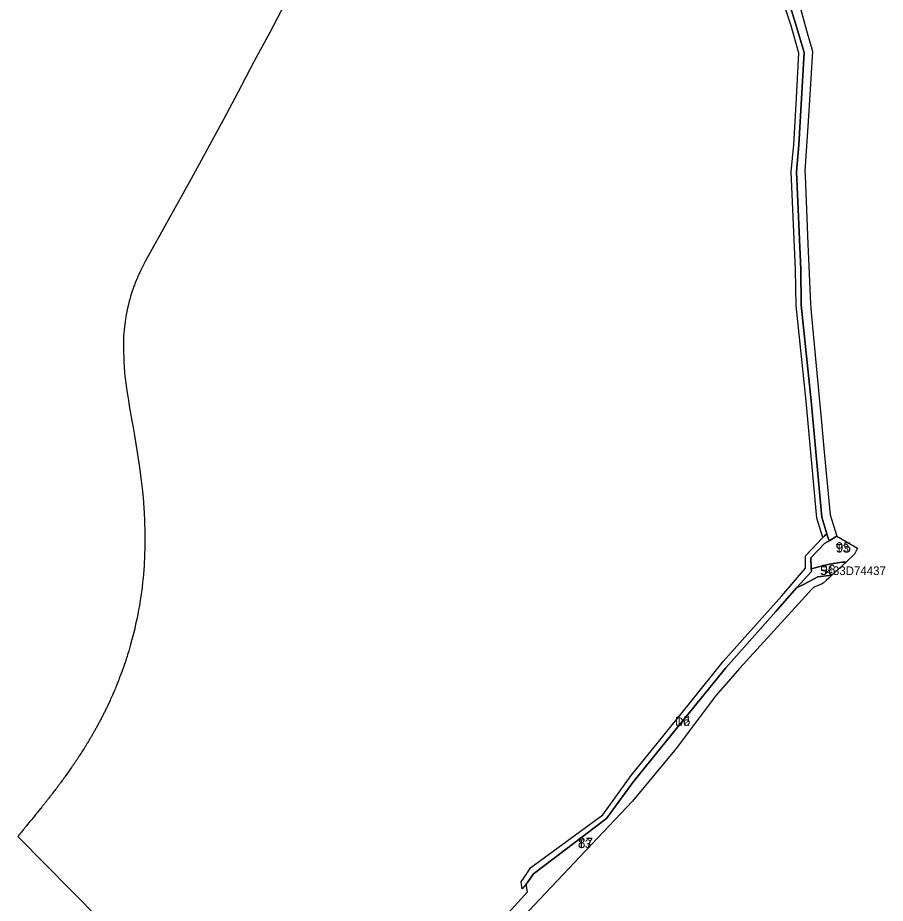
# Model space of a CAD drawing. Extents: x -537012 to -534603, y -1176562 to -1172739.
# Drawn here: x -536047 to -535541, y -1174648 to -1174132 of the extents above; entities that cross this region are included whole.
import ezdxf

# ---------------------------------------------------------------- set-up
doc = ezdxf.new("R2010")
doc.units = 0
for name, color, linetype in [('96120023', 7, 'Continuous'), ('96140023', 7, 'Continuous'), ('ID_VPS', 7, 'Continuous')]:
    doc.layers.add(name, color=color, linetype=linetype)

msp = doc.modelspace()

# ---------------------------------------------------------------- linework, layer by layer
at = {"layer": '96120023'}
for points in [[(-535891.53, -1174123.6), (-535900.28, -1174140.39), (-535909.37, -1174157.17), (-535919.16, -1174175.71), (-535927.21, -1174191.1), (-535946.09, -1174225.72), (-535972.84, -1174273.97), (-535973.9, -1174275.96), (-535974.53, -1174277.12), (-535974.84, -1174277.72), (-535975.24, -1174278.53), (-535975.67, -1174279.4), (-535976.07, -1174280.25), (-535976.35, -1174280.83), (-535976.73, -1174281.67), (-535977.01, -1174282.31), (-535977.27, -1174282.88), (-535977.37, -1174283.13), (-535977.48, -1174283.36), (-535977.5, -1174283.43), (-535977.53, -1174283.5), (-535977.56, -1174283.56), (-535977.58, -1174283.62), (-535977.6, -1174283.66), (-535977.63, -1174283.72), (-535977.66, -1174283.79), (-535977.69, -1174283.87), (-535977.72, -1174283.93), (-535977.73, -1174283.97), (-535977.81, -1174284.14), (-535977.89, -1174284.34), (-535977.93, -1174284.44), (-535978.03, -1174284.68), (-535978.16, -1174284.98), (-535978.26, -1174285.23), (-535978.35, -1174285.47), (-535978.58, -1174286.03), (-535978.72, -1174286.4), (-535978.97, -1174287.02), (-535979.24, -1174287.74), (-535979.46, -1174288.39), (-535979.94, -1174289.65), (-535980.49, -1174291.25), (-535981.01, -1174292.89), (-535981.47, -1174294.4), (-535981.93, -1174295.97), (-535982.21, -1174297.02), (-535982.72, -1174298.92), (-535983.04, -1174300.36), (-535983.44, -1174302.16), (-535983.81, -1174304.02), (-535984.18, -1174306.05), (-535984.66, -1174309.2), (-535985.05, -1174312.04), (-535985.49, -1174317.46), (-535985.58, -1174326.03), (-535985.4, -1174330.79), (-535985.37, -1174332.48), (-535985.21, -1174335.55), (-535984.98, -1174338.43), (-535984.73, -1174340.89), (-535984.44, -1174343.35), (-535984.24, -1174344.91), (-535984.07, -1174346.15), (-535983.79, -1174348.09), (-535983.24, -1174351.73), (-535982.73, -1174354.88), (-535982.18, -1174358.19), (-535981.62, -1174361.4), (-535980.68, -1174366.79), (-535979.99, -1174370.69), (-535979.16, -1174375.44), (-535978.54, -1174379.1), (-535977.73, -1174383.96), (-535976.93, -1174389.07), (-535976.21, -1174394.02), (-535975.23, -1174401.58), (-535974.52, -1174407.91), (-535973.96, -1174414.06), (-535973.93, -1174414.51), (-535973.89, -1174414.96), (-535973.85, -1174415.41), (-535973.82, -1174415.87), (-535973.79, -1174416.32), (-535973.75, -1174416.78), (-535973.72, -1174417.23), (-535973.63, -1174418.61), (-535973.57, -1174419.54), (-535973.43, -1174421.87), (-535973.34, -1174423.76), (-535973.25, -1174425.67), (-535973.09, -1174431.51), (-535973.09, -1174440.09), (-535973.53, -1174451.08), (-535973.74, -1174453.87), (-535973.92, -1174456.32), (-535974.14, -1174458.55), (-535974.4, -1174460.96), (-535974.7, -1174463.8), (-535974.92, -1174465.59), (-535975.27, -1174467.86), (-535975.62, -1174470.51), (-535976.06, -1174472.91), (-535976.32, -1174474.79), (-535976.8, -1174477.15), (-535977.24, -1174479.82), (-535977.81, -1174482.49), (-535978.51, -1174485.37), (-535979.03, -1174488.26), (-535979.91, -1174491.58), (-535980.61, -1174494.47), (-535981.66, -1174498.05), (-535982.53, -1174501.11), (-535983.14, -1174503.12), (-535983.51, -1174504.29), (-535983.98, -1174505.75), (-535984.29, -1174506.7), (-535986.55, -1174513.28), (-535987.3, -1174515.29), (-535987.6, -1174516.05), (-535988.02, -1174517.16), (-535988.33, -1174518), (-535988.71, -1174518.94), (-535989.24, -1174520.28), (-535989.6, -1174521.18), (-535989.89, -1174521.88), (-535990.18, -1174522.58), (-535990.5, -1174523.37), (-535991.02, -1174524.56), (-535991.54, -1174525.8), (-535991.98, -1174526.78), (-535992.48, -1174527.97), (-535993.05, -1174529.17), (-535993.4, -1174530.02), (-535995.11, -1174533.63), (-535995.31, -1174534.06), (-535995.54, -1174534.54), (-535995.78, -1174535.02), (-535996.01, -1174535.51), (-535996.25, -1174535.98), (-535996.48, -1174536.46), (-535996.72, -1174536.94), (-535996.96, -1174537.41), (-535997.2, -1174537.89), (-535997.44, -1174538.36), (-535997.68, -1174538.83), (-535997.91, -1174539.3), (-535998.15, -1174539.76), (-535998.4, -1174540.23), (-535998.64, -1174540.69), (-535998.88, -1174541.16), (-535999.12, -1174541.62), (-535999.36, -1174542.08), (-535999.61, -1174542.53), (-535999.85, -1174542.99), (-536000.09, -1174543.44), (-536000.34, -1174543.89), (-536000.58, -1174544.35), (-536000.83, -1174544.8), (-536001.07, -1174545.24), (-536001.32, -1174545.69), (-536001.56, -1174546.13), (-536001.81, -1174546.58), (-536002.06, -1174547.02), (-536002.3, -1174547.46), (-536002.55, -1174547.9), (-536002.8, -1174548.33), (-536003.05, -1174548.77), (-536003.3, -1174549.2), (-536003.54, -1174549.64), (-536003.79, -1174550.07), (-536004.04, -1174550.49), (-536004.29, -1174550.92), (-536004.54, -1174551.35), (-536004.79, -1174551.77), (-536005.04, -1174552.2), (-536005.29, -1174552.62), (-536005.54, -1174553.04), (-536005.79, -1174553.46), (-536006.04, -1174553.87), (-536006.54, -1174554.7), (-536006.79, -1174555.12), (-536007.04, -1174555.53), (-536007.55, -1174556.35), (-536007.8, -1174556.75), (-536008.05, -1174557.16), (-536008.55, -1174557.96), (-536009.06, -1174558.76), (-536009.81, -1174559.95), (-536010.32, -1174560.74), (-536011.32, -1174562.29), (-536012.08, -1174563.45), (-536012.33, -1174563.83), (-536012.58, -1174564.21), (-536012.83, -1174564.58), (-536013.09, -1174564.96), (-536013.34, -1174565.34), (-536013.59, -1174565.71), (-536013.84, -1174566.08), (-536014.09, -1174566.45), (-536014.34, -1174566.82), (-536014.59, -1174567.19), (-536014.84, -1174567.56), (-536015.09, -1174567.93), (-536015.34, -1174568.29), (-536015.59, -1174568.65), (-536015.84, -1174569.02), (-536016.59, -1174570.09), (-536017.59, -1174571.51), (-536018.58, -1174572.91), (-536019.57, -1174574.29), (-536019.82, -1174574.63), (-536020.31, -1174575.3), (-536020.8, -1174575.98), (-536021.29, -1174576.65), (-536021.77, -1174577.31), (-536022.26, -1174577.97), (-536022.5, -1174578.29), (-536022.75, -1174578.62), (-536022.99, -1174578.95), (-536023.23, -1174579.27), (-536023.47, -1174579.59), (-536023.71, -1174579.91), (-536023.98, -1174580.27), (-536024.22, -1174580.59), (-536024.7, -1174581.22), (-536025.17, -1174581.85), (-536025.65, -1174582.48), (-536026.12, -1174583.09), (-536027.06, -1174584.32), (-536027.3, -1174584.62), (-536027.53, -1174584.92), (-536027.76, -1174585.22), (-536027.99, -1174585.52), (-536028.23, -1174585.82), (-536028.46, -1174586.12), (-536028.92, -1174586.71), (-536029.15, -1174587), (-536029.38, -1174587.3), (-536029.61, -1174587.59), (-536029.84, -1174587.88), (-536030.06, -1174588.17), (-536030.29, -1174588.46), (-536030.52, -1174588.75), (-536030.74, -1174589.03), (-536030.97, -1174589.32), (-536031.19, -1174589.6), (-536031.42, -1174589.88), (-536031.64, -1174590.17), (-536031.86, -1174590.45), (-536032.09, -1174590.73), (-536032.31, -1174591.01), (-536032.53, -1174591.28), (-536032.75, -1174591.56), (-536032.97, -1174591.84), (-536033.19, -1174592.11), (-536033.41, -1174592.38), (-536033.85, -1174592.93), (-536034.06, -1174593.2), (-536034.5, -1174593.74), (-536034.71, -1174594), (-536035.35, -1174594.8), (-536035.78, -1174595.32), (-536036.2, -1174595.85), (-536036.62, -1174596.36), (-536037.04, -1174596.88), (-536037.45, -1174597.39), (-536038.07, -1174598.14), (-536038.47, -1174598.64), (-536038.88, -1174599.14), (-536039.08, -1174599.38), (-536039.48, -1174599.87), (-536040.07, -1174600.6), (-536040.47, -1174601.08), (-536040.86, -1174601.56), (-536041.44, -1174602.27), (-536042.01, -1174602.96), (-536042.01, -1174602.97), (-536042.02, -1174602.97), (-536042.02, -1174602.98), (-536042.03, -1174602.99), (-536042.03, -1174603), (-536042.04, -1174603), (-536042.04, -1174603.01), (-536042.05, -1174603.01), (-536042.06, -1174603.02), (-536042.06, -1174603.03), (-536042.07, -1174603.04), (-536042.07, -1174603.05), (-536042.08, -1174603.06), (-536042.09, -1174603.07), (-536042.1, -1174603.08), (-536042.11, -1174603.09), (-536042.12, -1174603.1), (-536042.13, -1174603.11), (-536042.13, -1174603.12), (-536042.14, -1174603.12), (-536042.14, -1174603.13), (-536042.15, -1174603.13), (-536042.15, -1174603.14), (-536042.16, -1174603.15), (-536042.17, -1174603.16), (-536042.17, -1174603.17), (-536042.21, -1174603.21), (-536042.25, -1174603.26), (-536042.29, -1174603.31), (-536042.36, -1174603.39), (-536042.4, -1174603.44), (-536042.45, -1174603.5), (-536042.5, -1174603.56), (-536042.66, -1174603.75), (-536042.86, -1174604.01), (-536043.05, -1174604.23), (-536043.2, -1174604.41), (-536043.54, -1174604.84), (-536043.96, -1174605.35), (-536044.61, -1174606.14), (-536045.11, -1174606.76), (-536045.23, -1174606.9), (-536045.38, -1174607.08), (-536045.5, -1174607.23), (-536045.65, -1174607.41), (-536045.73, -1174607.51), (-536045.86, -1174607.66), (-536045.99, -1174607.83), (-536046.08, -1174607.94), (-536046.31, -1174608.21), (-536046.49, -1174608.44), (-536046.66, -1174608.64), (-536046.81, -1174608.83), (-536046.92, -1174608.96), (-536047.02, -1174609.09), (-536047.12, -1174609.21), (-536047.2, -1174609.3), (-536047.23, -1174609.35), (-535999.47, -1174657.57)], [(-535597.91, -1174121.88), (-535593.49, -1174135.66), (-535588.73, -1174151.97), (-535591.8, -1174205.87), (-535593.27, -1174221.64), (-535590.7, -1174278.54), (-535590.36, -1174299.35), (-535584.54, -1174355.16), (-535578.34, -1174423.09), (-535575.43, -1174432.79), (-535576.99, -1174434.19), (-535577.9, -1174434.99), (-535581.3, -1174423.66), (-535587.52, -1174355.45), (-535593.35, -1174299.53), (-535593.7, -1174278.64), (-535596.28, -1174221.57), (-535594.79, -1174205.64), (-535593.45, -1174182.15), (-535591.76, -1174152.32), (-535596.36, -1174136.54), (-535600.68, -1174123.06)], [(-535765, -1174658.05), (-535749.98, -1174641.67), (-535750.85, -1174637.13), (-535748.27, -1174633.53), (-535746.46, -1174631.01), (-535703.99, -1174598.8), (-535689.14, -1174578.56), (-535687.99, -1174576.99), (-535665.63, -1174549.39), (-535634.43, -1174510.88), (-535605.25, -1174478.01), (-535593.09, -1174464.3), (-535589.02, -1174462.38), (-535580.79, -1174457.86), (-535572.49, -1174456.93), (-535574.25, -1174458.61), (-535575.88, -1174460.08), (-535577.56, -1174461.5), (-535578.67, -1174462.15), (-535582.05, -1174463.57), (-535583.18, -1174464.05), (-535583.58, -1174464.36), (-535584.26, -1174465.02), (-535587.97, -1174469.09), (-535626.48, -1174511.34), (-535631.37, -1174517.08), (-535640, -1174526.8), (-535663.42, -1174557.88), (-535688.83, -1174588.61), (-535712.62, -1174613.88), (-535752.69, -1174656.44)]]:
    msp.add_lwpolyline(points, dxfattribs=at)
for points in [[(-535577.9, -1174434.99), (-535576.99, -1174434.19), (-535575.43, -1174432.79), (-535574.87, -1174434.67), (-535574.22, -1174436.82), (-535576.86, -1174438.35), (-535584.81, -1174446.74), (-535584.57, -1174453.18), (-535584.51, -1174454.64), (-535593.09, -1174464.3), (-535605.25, -1174478.01), (-535634.43, -1174510.88), (-535665.63, -1174549.39), (-535687.99, -1174576.99), (-535689.14, -1174578.56), (-535703.99, -1174598.8), (-535746.46, -1174631.01), (-535748.27, -1174633.53), (-535750.85, -1174637.13), (-535753.14, -1174639.77), (-535753.67, -1174635.81), (-535752.02, -1174633.19), (-535748.07, -1174627.29), (-535706.15, -1174596.66), (-535689.66, -1174573.74), (-535673.59, -1174554.12), (-535655.58, -1174531.8), (-535635.91, -1174507.3), (-535624.77, -1174494.76), (-535601.81, -1174468.98), (-535587.88, -1174452.82), (-535587.95, -1174445.5), (-535578.18, -1174435.24)], [(-535564.26, -1174449.27), (-535566.58, -1174449.37), (-535574.22, -1174450.5), (-535584.57, -1174453.18), (-535584.81, -1174446.74), (-535576.86, -1174438.35), (-535574.22, -1174436.82), (-535569.6, -1174434.13), (-535557.53, -1174441.09), (-535559.27, -1174444.63)], [(-535593.09, -1174464.3), (-535584.51, -1174454.64), (-535584.57, -1174453.18), (-535574.22, -1174450.5), (-535566.58, -1174449.37), (-535564.26, -1174449.27), (-535572.49, -1174456.93), (-535580.79, -1174457.86), (-535589.02, -1174462.38)]]:
    msp.add_lwpolyline(points, close=True, dxfattribs=at)
at = {"layer": '96140023'}
msp.add_lwpolyline([(-535590.94, -1174126.38), (-535587.31, -1174139.14), (-535583.84, -1174151.31), (-535584.84, -1174167.22), (-535585.82, -1174182.88), (-535586.58, -1174194.95), (-535588.23, -1174221.28), (-535588.13, -1174223.73), (-535586.5, -1174263.53), (-535585.06, -1174298.6), (-535584.6, -1174303.58), (-535582.08, -1174330.65), (-535578.83, -1174365.59), (-535577.2, -1174383.07), (-535573.6, -1174421.76), (-535569.6, -1174434.13), (-535574.22, -1174436.82), (-535574.87, -1174434.67), (-535575.43, -1174432.79), (-535578.34, -1174423.09), (-535584.54, -1174355.16), (-535590.36, -1174299.35), (-535590.7, -1174278.54), (-535593.27, -1174221.64), (-535591.8, -1174205.87), (-535588.73, -1174151.97), (-535593.49, -1174135.66), (-535597.91, -1174121.88)], dxfattribs=at)

# ---------------------------------------------------------------- texts
at = {"layer": '96120023'}
for s, rotation, p in [('T3', 0, (-535570.34, -1174443.66)), ('D2', 360, (-535663.95, -1174544.74)), ('T3', 0, (-535720.68, -1174616.04))]:
    msp.add_text(s, height=5, rotation=rotation, dxfattribs=at).set_placement(p)
msp.add_text('5433D74437', height=5, dxfattribs=at).set_placement((-535579.37, -1174456.78))
at = {"layer": 'ID_VPS'}
for s, rotation, p in [('95', 360, (-535570.34, -1174443.66)), ('96', 360, (-535579.37, -1174456.78)), ('16', 0, (-535663.95, -1174544.74)), ('87', 360, (-535720.68, -1174616.04))]:
    msp.add_text(s, height=6, rotation=rotation, dxfattribs=at).set_placement(p)

doc.saveas('drawing.dxf')
